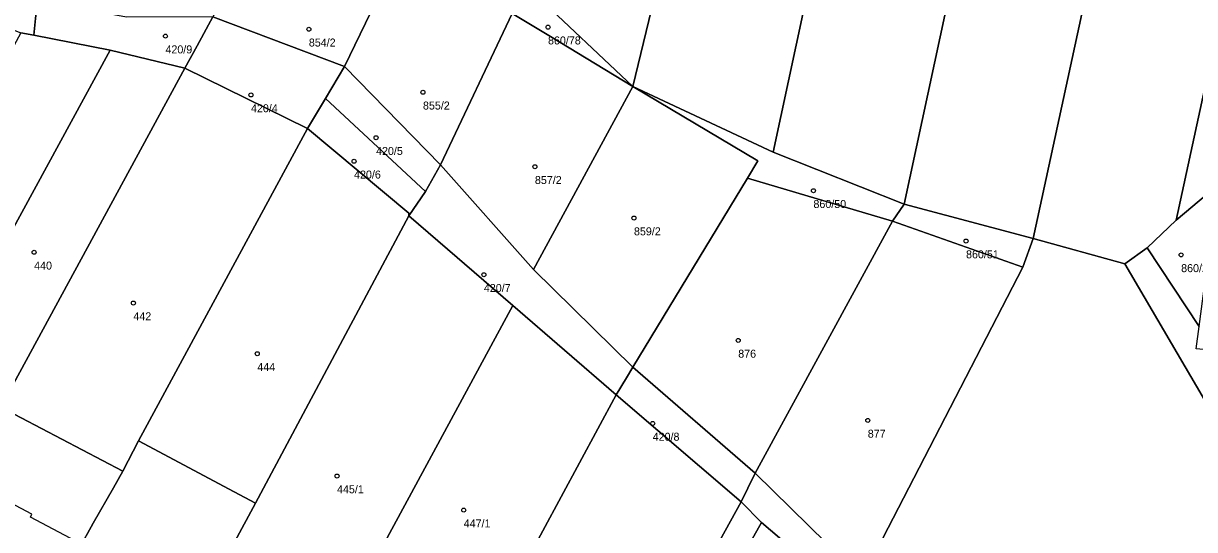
# Model space of a CAD drawing. Extents: x -587171 to -555306, y -1167727 to -1074732.
# Drawn here: x -585196.7 to -585050.4, y -1165585.9 to -1165522.6 of the extents above; entities that cross this region are included whole.
import ezdxf

# ---------------------------------------------------------------- set-up
doc = ezdxf.new("R2010")
doc.units = 0
for name, color, linetype in [('Definiční body', 7, 'Continuous'), ('Polygon budovy', 7, 'Continuous'), ('Polygon parcely', 7, 'Continuous')]:
    doc.layers.add(name, color=color, linetype=linetype)

msp = doc.modelspace()

# ---------------------------------------------------------------- linework, layer by layer
at = {"layer": 'Definiční body'}
for centre in [(-585161.05, -1165523.35), (-585131.16, -1165523.09), (-585178.97, -1165524.21), (-585168.28, -1165531.57), (-585146.79, -1165531.23), (-585152.65, -1165536.91), (-585155.4, -1165539.86), (-585132.8, -1165540.54), (-585097.99, -1165543.54), (-585120.42, -1165546.96), (-585195.38, -1165551.24), (-585078.92, -1165549.83), (-585052.04, -1165551.56), (-585139.18, -1165554.04), (-585182.98, -1165557.58), (-585107.39, -1165562.26), (-585167.49, -1165563.92), (-585118.08, -1165572.64), (-585091.2, -1165572.26), (-585157.53, -1165579.21), (-585141.7, -1165583.48)]:
    msp.add_circle(centre, 0.25, dxfattribs=at)
at = {"layer": 'Polygon budovy'}
msp.add_lwpolyline([(-585189.47, -1165587.73), (-585195.85, -1165584.35), (-585195.66, -1165584), (-585199.73, -1165581.85), (-585199.98, -1165582.32), (-585204.53, -1165579.91), (-585209.23, -1165588.68), (-585194.56, -1165596.57)], close=True, dxfattribs=at)
at = {"layer": 'Polygon parcely'}
for points in [[(-585095.33, -1165426.27), (-585071.65, -1165321.64), (-585078.73, -1165318.74), (-585085.42, -1165315.98), (-585088.26, -1165314.75), (-585108.41, -1165407.62), (-585132.85, -1165518.86), (-585120.57, -1165530.49)], [(-585077.64, -1165420.59), (-585056.47, -1165328.63), (-585062.87, -1165325.77), (-585069.26, -1165322.62), (-585071.65, -1165321.64), (-585095.33, -1165426.27), (-585120.57, -1165530.49), (-585103.04, -1165538.72)], [(-585062.62, -1165433.4), (-585039.8, -1165336.06), (-585056.47, -1165328.63), (-585077.64, -1165420.59), (-585103.04, -1165538.72), (-585086.66, -1165545.21)], [(-585045.59, -1165434.24), (-585024.23, -1165343.01), (-585039.8, -1165336.06), (-585062.62, -1165433.4), (-585086.66, -1165545.21), (-585070.55, -1165549.52)], [(-585028.83, -1165437.23), (-585008.06, -1165350.23), (-585024.23, -1165343.01), (-585045.59, -1165434.24), (-585070.55, -1165549.52), (-585059.09, -1165552.7), (-585056.3, -1165550.68), (-585052.65, -1165547.24)], [(-585008.06, -1165350.23), (-585028.83, -1165437.23), (-585052.65, -1165547.24), (-585043.78, -1165539.78), (-585038.06, -1165534.88), (-585031.88, -1165529.41), (-585029.25, -1165526.87), (-584991.33, -1165359.16)], [(-585166.17, -1165508.94), (-585173.05, -1165521.81), (-585156.61, -1165528.01), (-585149.42, -1165513.18)], [(-585149.42, -1165513.18), (-585156.61, -1165528.01), (-585144.58, -1165540.29), (-585135.64, -1165521.4)], [(-585195.19, -1165522.02), (-585195.4, -1165524.11), (-585185.86, -1165525.98), (-585176.53, -1165528.23), (-585175.01, -1165525.42), (-585173.05, -1165521.81), (-585183.82, -1165521.83), (-585194.97, -1165519.8)], [(-585135.64, -1165521.4), (-585130.87, -1165524.27), (-585124.07, -1165528.38), (-585120.57, -1165530.49), (-585132.85, -1165518.86)], [(-585124.07, -1165528.38), (-585130.87, -1165524.27), (-585135.64, -1165521.4), (-585144.58, -1165540.29), (-585132.97, -1165553.39), (-585120.57, -1165530.49)], [(-585161.23, -1165535.74), (-585158.99, -1165531.99), (-585156.61, -1165528.01), (-585173.05, -1165521.81), (-585175.01, -1165525.42), (-585176.53, -1165528.23)], [(-585217.07, -1165561.01), (-585207.77, -1165566.09), (-585185.86, -1165525.98), (-585195.4, -1165524.11), (-585197.05, -1165523.79)], [(-585176.53, -1165528.23), (-585185.86, -1165525.98), (-585207.77, -1165566.09), (-585202.2, -1165569.14), (-585199.54, -1165570.59)], [(-585182.32, -1165574.83), (-585161.23, -1165535.74), (-585176.53, -1165528.23), (-585199.54, -1165570.59), (-585184.3, -1165578.61)], [(-585146.49, -1165543.65), (-585144.58, -1165540.29), (-585156.61, -1165528.01), (-585158.99, -1165531.99)], [(-585106.24, -1165541.99), (-585104.93, -1165539.81), (-585120.57, -1165530.49), (-585132.97, -1165553.39), (-585120.57, -1165565.59)], [(-585103.04, -1165538.72), (-585120.57, -1165530.49), (-585104.93, -1165539.81), (-585106.24, -1165541.99), (-585088.1, -1165547.35), (-585086.66, -1165545.21)], [(-585148.54, -1165546.69), (-585146.49, -1165543.65), (-585158.99, -1165531.99), (-585161.23, -1165535.74), (-585148.55, -1165546.34)], [(-585148.54, -1165546.69), (-585148.55, -1165546.34), (-585161.23, -1165535.74), (-585182.32, -1165574.83), (-585170.37, -1165581.2), (-585167.72, -1165582.62)], [(-585148.54, -1165546.69), (-585135.54, -1165557.91), (-585122.64, -1165569.08), (-585121.36, -1165566.92), (-585120.57, -1165565.59), (-585132.97, -1165553.39), (-585144.58, -1165540.29), (-585146.49, -1165543.65)], [(-585056.3, -1165550.68), (-585049.78, -1165560.5), (-585047.99, -1165546.92), (-585042.74, -1165545.42), (-585043.78, -1165539.78), (-585052.65, -1165547.24)], [(-585088.1, -1165547.35), (-585106.24, -1165541.99), (-585120.57, -1165565.59), (-585105.28, -1165578.87)], [(-585070.55, -1165549.52), (-585086.66, -1165545.21), (-585088.1, -1165547.35), (-585071.84, -1165553.09)], [(-585156.66, -1165596.91), (-585154.74, -1165593.37), (-585157.68, -1165591.78), (-585155.27, -1165587.35), (-585152.34, -1165588.93), (-585135.54, -1165557.91), (-585148.54, -1165546.69), (-585167.72, -1165582.62), (-585170.31, -1165587.39), (-585173.82, -1165594.15), (-585175.04, -1165596.37), (-585174.87, -1165596.47), (-585179.33, -1165604.76), (-585180.46, -1165606.59), (-585166.13, -1165614.39), (-585164.04, -1165610.54), (-585171.63, -1165606.43), (-585169.26, -1165602.14), (-585168.31, -1165602.61), (-585166.89, -1165598.69), (-585167.15, -1165598.53), (-585165.1, -1165594.72), (-585161.17, -1165596.83), (-585160.25, -1165595.14)], [(-585105.28, -1165578.87), (-585091.9, -1165592), (-585071.84, -1165553.09), (-585088.1, -1165547.35)], [(-585070.55, -1165549.52), (-585071.84, -1165553.09), (-585091.9, -1165592), (-585055.17, -1165624.32), (-585031.98, -1165644.4), (-585018.8, -1165629.48), (-585024.78, -1165620.83), (-585034.75, -1165608.81), (-585042.8, -1165596.99), (-585042.52, -1165586.93), (-585046.7, -1165573.82), (-585059.09, -1165552.7)], [(-585039.17, -1165587.87), (-585041.6, -1165572.82), (-585047.78, -1165563.52), (-585050.15, -1165563.3), (-585049.78, -1165560.5), (-585056.3, -1165550.68), (-585059.09, -1165552.7), (-585046.7, -1165573.82), (-585042.52, -1165586.93), (-585042.8, -1165596.99), (-585034.75, -1165608.81), (-585024.78, -1165620.83), (-585018.8, -1165629.48), (-585016.64, -1165627.11), (-585024.6, -1165616.51), (-585036.23, -1165602.56), (-585039.37, -1165595.47)], [(-585138.7, -1165598.82), (-585122.64, -1165569.08), (-585135.54, -1165557.91), (-585152.34, -1165588.93), (-585153.41, -1165590.9)], [(-585121.36, -1165566.92), (-585122.64, -1165569.08), (-585107.02, -1165582.44), (-585106.19, -1165580.73), (-585105.28, -1165578.87), (-585120.57, -1165565.59)], [(-585151.43, -1165622.4), (-585144.52, -1165626.17), (-585143.26, -1165623.78), (-585141.4, -1165620.35), (-585142.83, -1165619.54), (-585142.06, -1165618.15), (-585142.41, -1165617.87), (-585139.8, -1165613.14), (-585137.47, -1165614.45), (-585130.09, -1165600.94), (-585122.02, -1165605.26), (-585120.16, -1165606.25), (-585107.02, -1165582.44), (-585122.64, -1165569.08), (-585138.7, -1165598.82)], [(-585184.3, -1165578.61), (-585199.54, -1165570.59), (-585204.53, -1165579.91), (-585209.23, -1165588.68), (-585210.32, -1165590.79), (-585195.71, -1165598.52), (-585194.56, -1165596.57), (-585189.47, -1165587.73), (-585188.71, -1165586.38), (-585187.99, -1165585.12), (-585185.47, -1165580.68)], [(-585180.46, -1165606.59), (-585179.33, -1165604.76), (-585174.87, -1165596.47), (-585175.04, -1165596.37), (-585173.82, -1165594.15), (-585170.31, -1165587.39), (-585167.72, -1165582.62), (-585170.37, -1165581.2), (-585182.32, -1165574.83), (-585184.3, -1165578.61), (-585185.47, -1165580.68), (-585187.99, -1165585.12), (-585188.71, -1165586.38), (-585189.47, -1165587.73), (-585194.56, -1165596.57), (-585195.71, -1165598.52)], [(-585092.37, -1165593.3), (-585091.9, -1165592), (-585105.28, -1165578.87), (-585106.19, -1165580.73), (-585107.02, -1165582.44), (-585104.5, -1165585.04), (-585092.95, -1165594.88)], [(-585117.25, -1165607.81), (-585104.5, -1165585.04), (-585107.02, -1165582.44), (-585120.16, -1165606.25)], [(-585092.95, -1165594.88), (-585104.5, -1165585.04), (-585117.25, -1165607.81), (-585103.86, -1165614.98)]]:
    msp.add_lwpolyline(points, close=True, dxfattribs=at)
msp.add_lwpolyline([(-585270.91, -1165503.96), (-585257.18, -1165504.24), (-585243.97, -1165507.84), (-585224.66, -1165514.03), (-585210.23, -1165518.54), (-585197.05, -1165523.79), (-585195.4, -1165524.11), (-585195.19, -1165522.02), (-585194.97, -1165519.8), (-585197.51, -1165518.93), (-585208.3, -1165515.23), (-585212.6, -1165513.65), (-585222.76, -1165509.92), (-585225.94, -1165508.95), (-585240.64, -1165504.46), (-585242.08, -1165504.02), (-585255.53, -1165500.73), (-585269.94, -1165498.81), (-585284.13, -1165499.44)], dxfattribs=at)

# ---------------------------------------------------------------- texts
at = {"layer": 'Definiční body'}
for s, p in [('854/2', (-585161.05, -1165525.51)), ('860/78', (-585131.16, -1165525.25)), ('420/9', (-585178.97, -1165526.37)), ('420/4', (-585168.28, -1165533.73)), ('855/2', (-585146.79, -1165533.39)), ('420/5', (-585152.65, -1165539.07)), ('420/6', (-585155.4, -1165542.02)), ('857/2', (-585132.8, -1165542.7)), ('860/50', (-585097.99, -1165545.7)), ('859/2', (-585120.42, -1165549.12)), ('860/51', (-585078.92, -1165551.99)), ('440', (-585195.38, -1165553.4)), ('860/25', (-585052.04, -1165553.72)), ('420/7', (-585139.18, -1165556.2)), ('442', (-585182.98, -1165559.74)), ('876', (-585107.39, -1165564.42)), ('444', (-585167.49, -1165566.08)), ('420/8', (-585118.08, -1165574.8)), ('877', (-585091.2, -1165574.42)), ('445/1', (-585157.53, -1165581.37)), ('447/1', (-585141.7, -1165585.64))]:
    msp.add_text(s, height=1, dxfattribs=at).set_placement(p)

doc.saveas('drawing.dxf')
